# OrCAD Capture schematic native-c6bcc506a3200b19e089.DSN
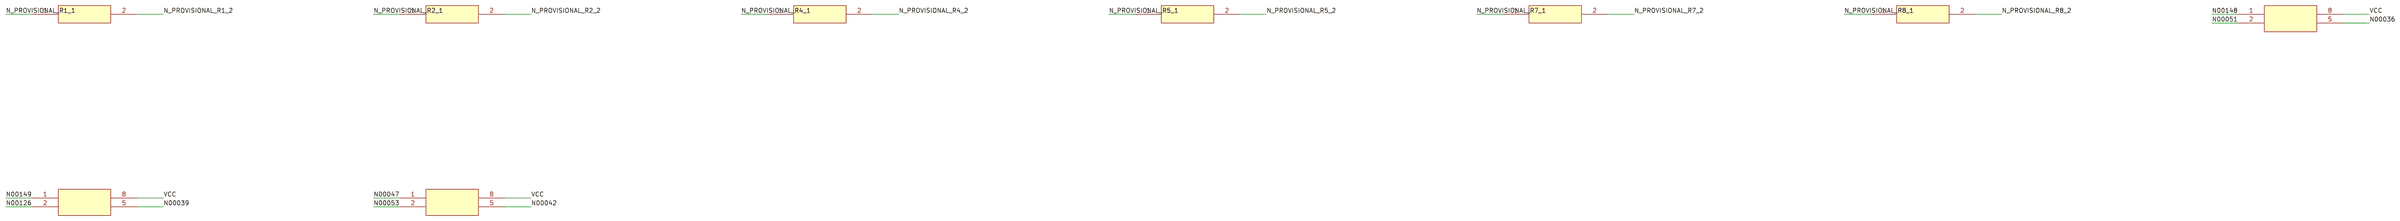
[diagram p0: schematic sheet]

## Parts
R1  100K1
R2  470K1
R4  100K1
R5  1470K1
R7  100K1
R8  470K1
U1  UNKNOWN
U2  UNKNOWN
U3  UNKNOWN

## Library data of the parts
R1 = OBS_R1
R2 = OBS_R2
R4 = OBS_R4
R5 = OBS_R5
R7 = OBS_R7
R8 = OBS_R8
U1 = OBS_U1
U2 = OBS_U2
U3 = OBS_U3

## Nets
VCC: U1.8 U2.8 U3.8
N_PROVISIONAL_R1_1: R1.1
N_PROVISIONAL_R1_2: R1.2
N_PROVISIONAL_R2_1: R2.1
N_PROVISIONAL_R2_2: R2.2
N_PROVISIONAL_R4_1: R4.1
N_PROVISIONAL_R4_2: R4.2
N_PROVISIONAL_R5_1: R5.1
N_PROVISIONAL_R5_2: R5.2
N_PROVISIONAL_R7_1: R7.1
N_PROVISIONAL_R7_2: R7.2
N_PROVISIONAL_R8_1: R8.1
N_PROVISIONAL_R8_2: R8.2

Not connected (* = marked no-connect by the designer): U1 1 2 5; U2 1 2 5; U3 1 2 5
